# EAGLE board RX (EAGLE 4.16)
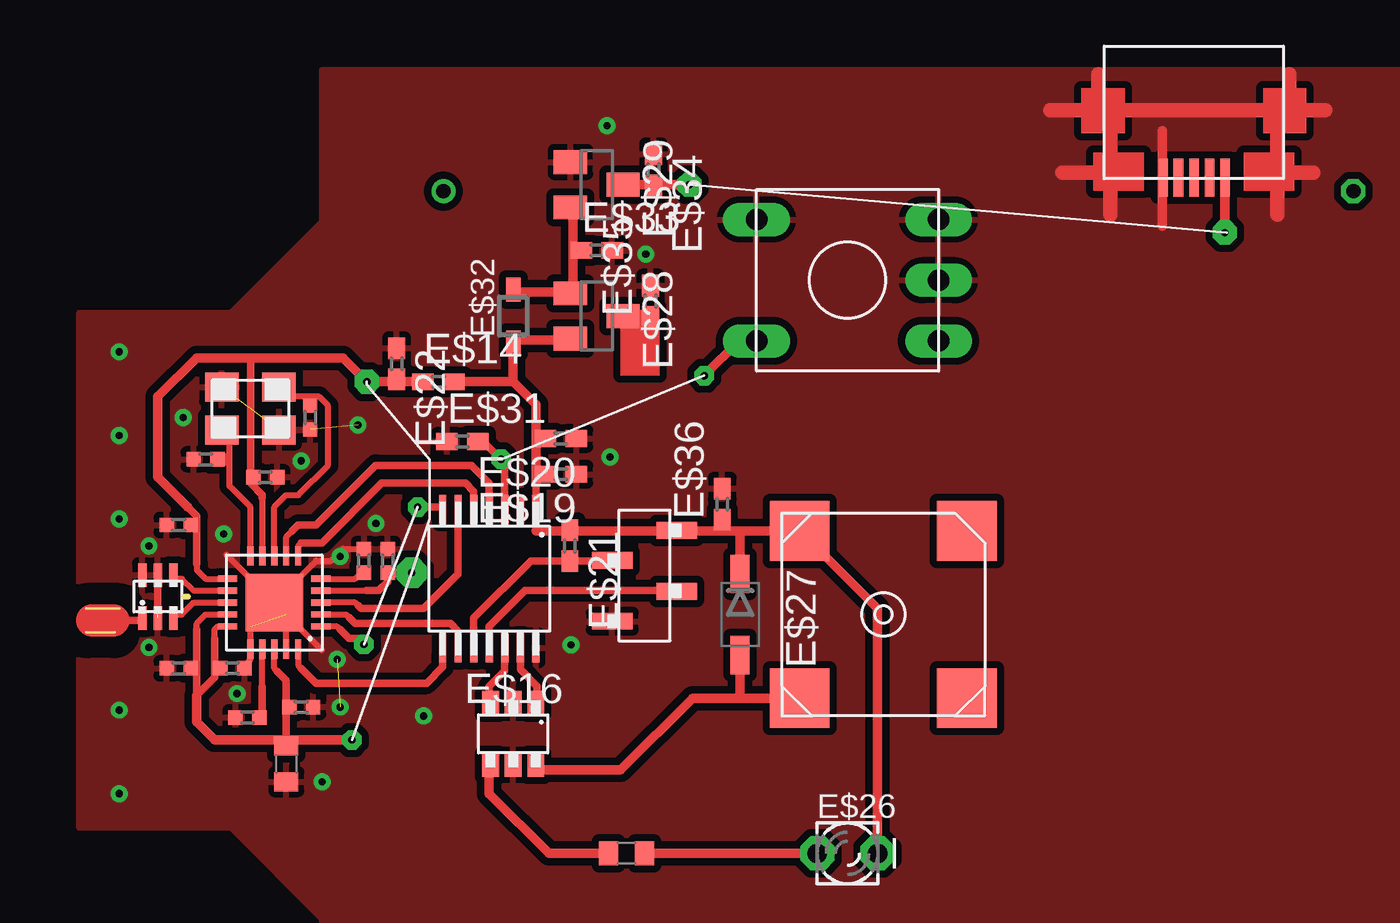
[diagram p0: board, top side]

Size 4.25 x 1.5 mm. Coordinates in mm from the lower left corner, seen from the top.
Outline: 4.12,1.5 4.25,1.5
Outline: 1.19,0 0,0
Outline: 1.38,1 0,1
Copper layers (1*16): Top 0.035mm / dielectric 1.5mm / Bottom 0.035mm
Design rules "default": minimum track width 10mil, minimum drill 24mil, track to track 8mil, track to pad 8mil, pad to pad 8mil, via to via 8mil, smd to smd 8mil, copper to edge 40mil, drill to drill 8mil, minimum pad ring 10mil, minimum via ring 8mil, stop-mask expansion 4mil, vias tented up to drill 0mil, thermal gap 10mil

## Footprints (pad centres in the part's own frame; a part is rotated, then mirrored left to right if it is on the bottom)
QFN20 = smd 0.8 x 0.26: 1 -1.95,1; 2 -1.95,0.5; 3 -1.95,0; 4 -1.95,-0.5; 5 -1.95,-1; 11 1.95,-1; 12 1.95,-0.5; 13 1.95,0; 14 1.95,0.5; 15 1.95,1 | smd 0.26 x 0.8: 6 -1,-1.95; 7 -0.5,-1.95; 8 0,-1.95; 9 0.5,-1.95; 10 1,-1.95; 16 1,1.95; 17 0.5,1.95; 18 0,1.95; 19 -0.5,1.95; 20 -1,1.95 | smd 2.4 x 2.4: EP 0,0
BALUN = smd 1 x 0.35: 1 -0.9,0.65; 2 -0.9,0; 3 -0.9,-0.65; 4 0.9,-0.65; 5 0.9,0; 6 0.9,0.65
NX3225GA = smd 1.4 x 1.2: 1 -1.2,-0.9; 2 1.2,-0.9; 3 1.2,0.9; 4 -1.2,0.9
C0402N = smd 0.6 x 0.6: 1 0.5,0; 2 -0.5,0
C0402 = smd 0.9 x 0.7: 1 -0.65,0; 2 0.65,0
C0603N = smd 0.8 x 1: 1 -0.75,0; 2 0.75,0
PW14 = smd 0.3 x 1.2: 1 -1.95,-2.9; 2 -1.3,-2.9; 3 -0.65,-2.9; 4 0,-2.9; 5 0.65,-2.9; 6 1.3,-2.9; 7 1.95,-2.9; 8 1.95,2.9; 9 1.3,2.9; 10 0.65,2.9; 11 0,2.9; 12 -0.65,2.9; 13 -1.3,2.9; 14 -1.95,2.9
SUPERSOT-6 = smd 0.7 x 1: P$1 -0.95,1.3; P$2 0,1.3; P$3 0.95,1.3; P$4 -0.95,-1.3; P$5 0,-1.3; P$6 0.95,-1.3
HEADERS4 = smd 0.7 x 1.7: P$1 1.27,1.35; P$3 -1.28,1.35; P$4 -0.03,-1.35; P$5 2.52,-1.35
ST-03CH = smd 2.5 x 2.5: P$1 -3.5,3.5; P$2 3.5,3.5; P$3 3.5,-3.5; P$4 -3.5,-3.5
SW_TACT_KSCL = drill 0.9 long: 1 -3.81,2.54; 2 -3.81,-2.54; 3 3.81,-2.54; 4 3.81,2.54; 5 -3.81,0
LD260 = drill 0.813 octagon: A -1.27,0; K 1.27,0
SOD123 = smd 1.6 x 0.8: 1 -1.7,0; 2 1.7,0
SOT23 = smd 1 x 1.4: 1 -0.95,-1.1; 2 0.95,-1.1; 3 0,1.1
MICRO-USB = smd 1.6 x 0.4: 1 -0.55,1.3; 2 -0.55,0.65; 3 -0.55,0; 4 -0.55,-0.65; 5 -0.55,-1.3
SOD323 = smd 1 x 0.6: 1 -1.1,0; 2 1.1,0

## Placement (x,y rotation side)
E$1  [QFN20]  7.88,1.25 180 top
E$2  [BALUN]  3,1.5 90 top
E$3  [NX3225GA]  not placed on the board
E$4  [C0402N]  11.62,3 90 top  (outside the outline)
E$5  [C0402N]  not placed on the board
E$6  [C0402N]  not placed on the board
E$7  [C0402N]  not placed on the board
E$8  [C0402N]  3.88,4.5 0 top
E$9  [C0402N]  not placed on the board
E$10  [C0402N]  6.12,-1.5 0 top
E$11  [C0402N]  3.88,-1.5 180 top
E$12  [C0402N]  not placed on the board
E$13  [C0402N]  9,-3.12 180 top  (outside the outline)
E$14  [C0402]  not placed on the board
E$15  [C0603N]  not placed on the board
E$16  [PW14]  not placed on the board
E$17  [SUPERSOT-6]  not placed on the board
E$18  [HEADERS4]  not placed on the board
E$19  [C0402]  not placed on the board
E$20  [C0402]  not placed on the board
E$21  [C0402]  not placed on the board
E$22  [C0402]  not placed on the board
E$23  [C0603N]  22.62,-9.25 0 top  (outside the outline)
E$24  [ST-03CH]  not placed on the board
E$25  [SW_TACT_KSCL]  not placed on the board
E$26  [LD260]  not placed on the board
E$27  [SOD123]  not placed on the board
E$28  [SOT23]  not placed on the board
E$29  [SOT23]  not placed on the board
E$30  [MICRO-USB]  not placed on the board
E$31  [C0402]  not placed on the board
E$32  [SOD323]  not placed on the board
E$33  [C0402]  not placed on the board
E$34  [C0402]  not placed on the board
E$35  [C0402]  not placed on the board
E$36  [C0402]  not placed on the board

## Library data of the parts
E$1 E$2 = texas
E$3 = crystal
E$4-E$15 E$19-E$23 E$28 E$29 E$31-E$36 = ref-packages
E$16 = TI_MSP430_v122
E$17 E$18 E$25 = sb
E$24 = csci381
E$26 = led
E$27 = smd-ipc
E$30 = con-amp

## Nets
GND: E$2.2 E$2.5 E$2.6 E$3.2 E$3.4 E$4.1 E$5.1 E$6.2 E$7.2 E$8.2 E$9.1 E$10.1 E$11.1 E$12.2 E$13.2 E$15.2 E$16.14 E$17.P$2 E$17.P$5 E$18.P$3 E$19.1 E$20.1 E$22.1 E$25.2 E$25.3 E$25.5 E$29.1 E$31.1 E$33.2 E$34.1 E$35.2 E$36.2
PWR: E$1.11
S$1: E$1.4
S$3: E$1.5
S$4: E$1.10
S$5: E$1.6
S$6: E$1.7
S$7: E$1.8
S$9: E$1.12
S$10: E$1.13
S$13: E$1.17
S$14: E$1.14 E$1.15 E$1.18 E$13.1
S$15: E$1.20
S$22: E$1.2
S$23: E$1.1
S$30: E$23.2

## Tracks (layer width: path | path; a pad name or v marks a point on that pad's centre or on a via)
GND  (via drill 0.3)  (5 unrouted)
  Top 0.254: E$4.1 10.75,3.5 10.25,3 9.62,3 6.88,0.25 6.88,-1.12 6.62,-1.38 E$10.1 | 8.38,0.75 9.88,-0.75 | 8.38,0.75 5.88,3.25 | 8.38,-0.5 8.38,0.75
  Top 0.305: 3,2 3,1
  Top 0.406: 49.88,21.5 50.38,21.5 | 45.06,17.01 45.06,21.01
  Top 0.61: 42.38,23.38 42.38,21.5 42.88,21.5 42.88,19.25 | 42.88,19.25 42.88,17.5 | 42.88,19.25 40.88,19.25 | 40.38,21.88 51.88,21.88 | 50.38,21.5 50.38,23.38 | 49.88,19.25 49.88,21.5 | 49.88,19.25 49.88,17.5 | 49.88,19.25 51.38,19.25
  other vias: 1.38,-6.75 1.38,-3.25 9.88,-6.25 2.62,-0.62 6.31,-2.56 10.5,-1.12 10.62,-3.12 1.38,4.75 2.62,3.62 1.38,8.25 5.75,4.12 1.38,11.75 4.06,9 12.12,4.56 10.62,3.19 11.38,8.69 20.3,-0.52 9,7.19 21.93,7.35 14.12,-3.5 23.43,15.85 21.8,21.23
  pour Top (isolate 0.305): 58.13,-18.35 9.88,-18.35 9.88,-12 6.06,-8.19 -0.29,-8.19 -0.29,13.4 6.06,13.4 9.88,17.21 9.88,17.21 9.88,23.56 58.13,23.56 58.13,17.21 58.13,-12
PWR
  Top 0.254: 7.38,5.62 7.38,3.12 | E$1.11 5,2.25 4.62,2.62 4.62,2.88
  Top 0.305: 7.38,5.62 7.38,5.75 6.88,6.25 6.88,11.5 | 4.25,5.25 4.62,4.88 4.62,2.88
  Top 0.406: 13.88,10.5 11.75,10.5 10.75,11.5 6.88,11.5 4.62,11.5 3,9.88 3,6.5 4.25,5.25
S$1  (via drill 0.3 pad 1.27)
  Top 0.254: E$1.4 11.75,1.75
  Top 0.305: 12.62,2.5 12.62,2.12 12.25,1.75 11.75,1.75
  Top 0.406: 12.62,2.5 v13.62,2.5
S$2  (via drill 0.6)
  other vias: 14.96,-13.27
S$3
  Top 0.254: E$1.5 11.25,2.25 11.5,2.5 11.62,2.5
S$4
  Top 0.254: E$1.10 6.88,5.25 6,6.12 6,8.38
S$5
  Top 0.254: E$1.6 8.88,3.62 9,3.75
  Top 0.305: 9,3.75 9.88,3.75 12.38,6.25 15.88,6.25 16.23,5.9 16.23,5.25
S$6
  Top 0.254: E$1.7 8.38,4 8.62,4.25
  Top 0.305: 8.62,4.25 8.88,4.5 9.62,4.5 12.12,7 16.12,7 16.88,6.25 16.88,5.38 16.88,5.25
S$7
  Top 0.254: E$1.8 7.88,5.25 8.38,5.75 8.88,5.75 10.12,7 10.12,9.5 9.75,9.88 8.38,9.88
S$8
  Top 0.406: 15.5,10.5 17.88,10.5 18.82,9.55 18.82,6.25
S$9
  Top 0.254: E$1.12 4.5,1.75 4,2.25 3.62,2.25
S$10
  Top 0.254: E$1.13 4.5,1.25 4,0.75 3.62,0.75
S$11
  Top 0.305: 1.12,0.5 2.25,0.5
  Top 1.36: 1.12,0.5 0.25,0.5
S$12  (via drill 0.3 pad 0.81)
  other vias: 11.12,-4.5
S$13
  Top 0.254: 7.38,-2.25 E$1.17
  Top 0.305: 7.38,-3.5 7.38,-2.25
S$14
  Top 0.254: 8,-1.62 7.88,-1.5 E$1.18 | E$1.15 5.5,0.25 5.38,0.12 5.38,-0.25 | E$1.14 5,0.75 4.62,0.38 4.62,0.12 | 8.38,-2.12 8.38,-2
  Top 0.305: 8.38,-2 8,-1.62 | 8.38,-3.25 8.38,-2.12 | 5.38,-0.25 5.38,-1.88 4.62,-2.62 4.62,0.12 | 8.38,-4.5 8.38,-3.25 | 8.38,-3.25 E$13.1
  Top 0.406: 11.12,-4.5 8.38,-4.5 5.38,-4.5 4.62,-3.75 4.62,-2.62
S$15
  Top 0.254: E$1.20 8.88,-1.38 9,-1.5
  Top 0.305: 9,-1.5 9.62,-2.12 14.25,-2.12 14.93,-1.45 14.93,-0.88
S$16
  Top 0.305: 22.15,3 18.62,3 16.23,0.6 16.23,-0.38
S$17
  Top 0.305: 24.38,1.75 18.38,1.75 16.88,0.25 16.88,-0.25
S$18
  Top 0.305: 18.82,4.25 18.82,6.25
  Top 0.406: 18.82,4.25 27.38,4.25 | 27.38,4.25 29.38,4.25 | 27.38,4.25 27.38,2.75
S$19  (via drill 0.3 pad 1.02)
  other vias: 47.67,16.75
S$20
  Top 0.254: 9.88,1.25 11.25,1.25 11.38,1.12
  Top 0.305: 11.38,1.12 11.5,1 14.12,1 15.57,2.45 15.57,4.88
S$21
  Top 0.406: 18.88,-5.75 22.38,-5.75 25.38,-2.75 27.38,-2.75 | 27.38,-2.75 28.88,-2.75 | 27.38,-2.75 27.38,-1.25
S$22
  Top 0.254: E$1.2 10.88,0.75 11,0.62
  Top 0.305: 11,0.62 11.25,0.38 15.25,0.38 15.57,0.05 15.57,-0.38
S$23
  Top 0.254: E$1.1 10.5,0.25 10.62,0.12
  Top 0.305: 10.62,0.12 11,-0.25 11.38,-0.25 11.62,-0.5
S$24  (via drill 0.3 pad 0.81)
  Top 0.305: 17.52,5.23 17.52,7.1 v17.38,7.25 16.6,8.02
S$25
  Top 0.406: 21.88,-9.25 19.38,-9.25 16.88,-6.75 16.88,-5.75
S$26
  Top 0.406: 30.38,3.75 33.12,1 33.12,-9.25
S$27  (via drill 0.3 pad 0.81)
  Top 0.406: v25.88,10.75 27.38,12.25 28.02,12.25
S$28  (via drill 0.3 pad 0.81)
  Top 0.305: v13.88,5.25 14.88,5.25
S$29  (via drill 0.6)
  other vias: 14.96,18.48
S$30
  Top 0.406: E$23.2 30.38,-9.25
S$31  (via drill 0.6)
  other vias: 53.05,18.48
S$32  (via drill 0.6)
  other vias: 53.05,-13.27
S$33
  Top 0.305: 16.88,-2.82 16.88,-2.25 17.27,-1.85 17.52,-1.6 17.52,-0.82
S$34  (via drill 0.3 pad 1.02)
  other vias: 11.75,10.5
S$35  (via drill 0.3 pad 0.81)
  other vias: 11.62,-0.5
S$36  (via drill 0.5 pad 1.42)
  other vias: 33.12,-9.25
S$37
  Top 0.305: 18.18,-1.07 18.18,-1.55 18.88,-2.25 18.88,-2.75
S$38
  Top 0.406: 20.38,17.75 20.38,14.25 17.88,14.25
S$39
  Top 0.406: 19.88,12.25 17.88,12.25 17.88,10.5
S$40  (via drill 0.5 pad 1.42)
  other vias: 30.62,-9.25
S$41
  Top 0.406: 22.88,18.75 25.25,18.75
S$42
  Top 0.406: 47.67,16.5 47.67,19.5
S$43  (via drill 0.3 pad 1.02)
  other vias: 25.25,18.75
(copper drawn outside any net)
  shapes: Top area x2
